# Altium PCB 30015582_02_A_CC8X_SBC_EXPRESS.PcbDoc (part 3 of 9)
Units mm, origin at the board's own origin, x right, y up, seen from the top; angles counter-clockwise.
Board outline 87 x 63 mm, 6 copper layers (Top Layer-L1, GND Plane-L2, Signal-L3, PWR/Signal-L4, GND Plane-L5, Bottom Layer-L6), stack 1.172 mm thick; 169 components, 171 nets, 693 pads, 391 vias.
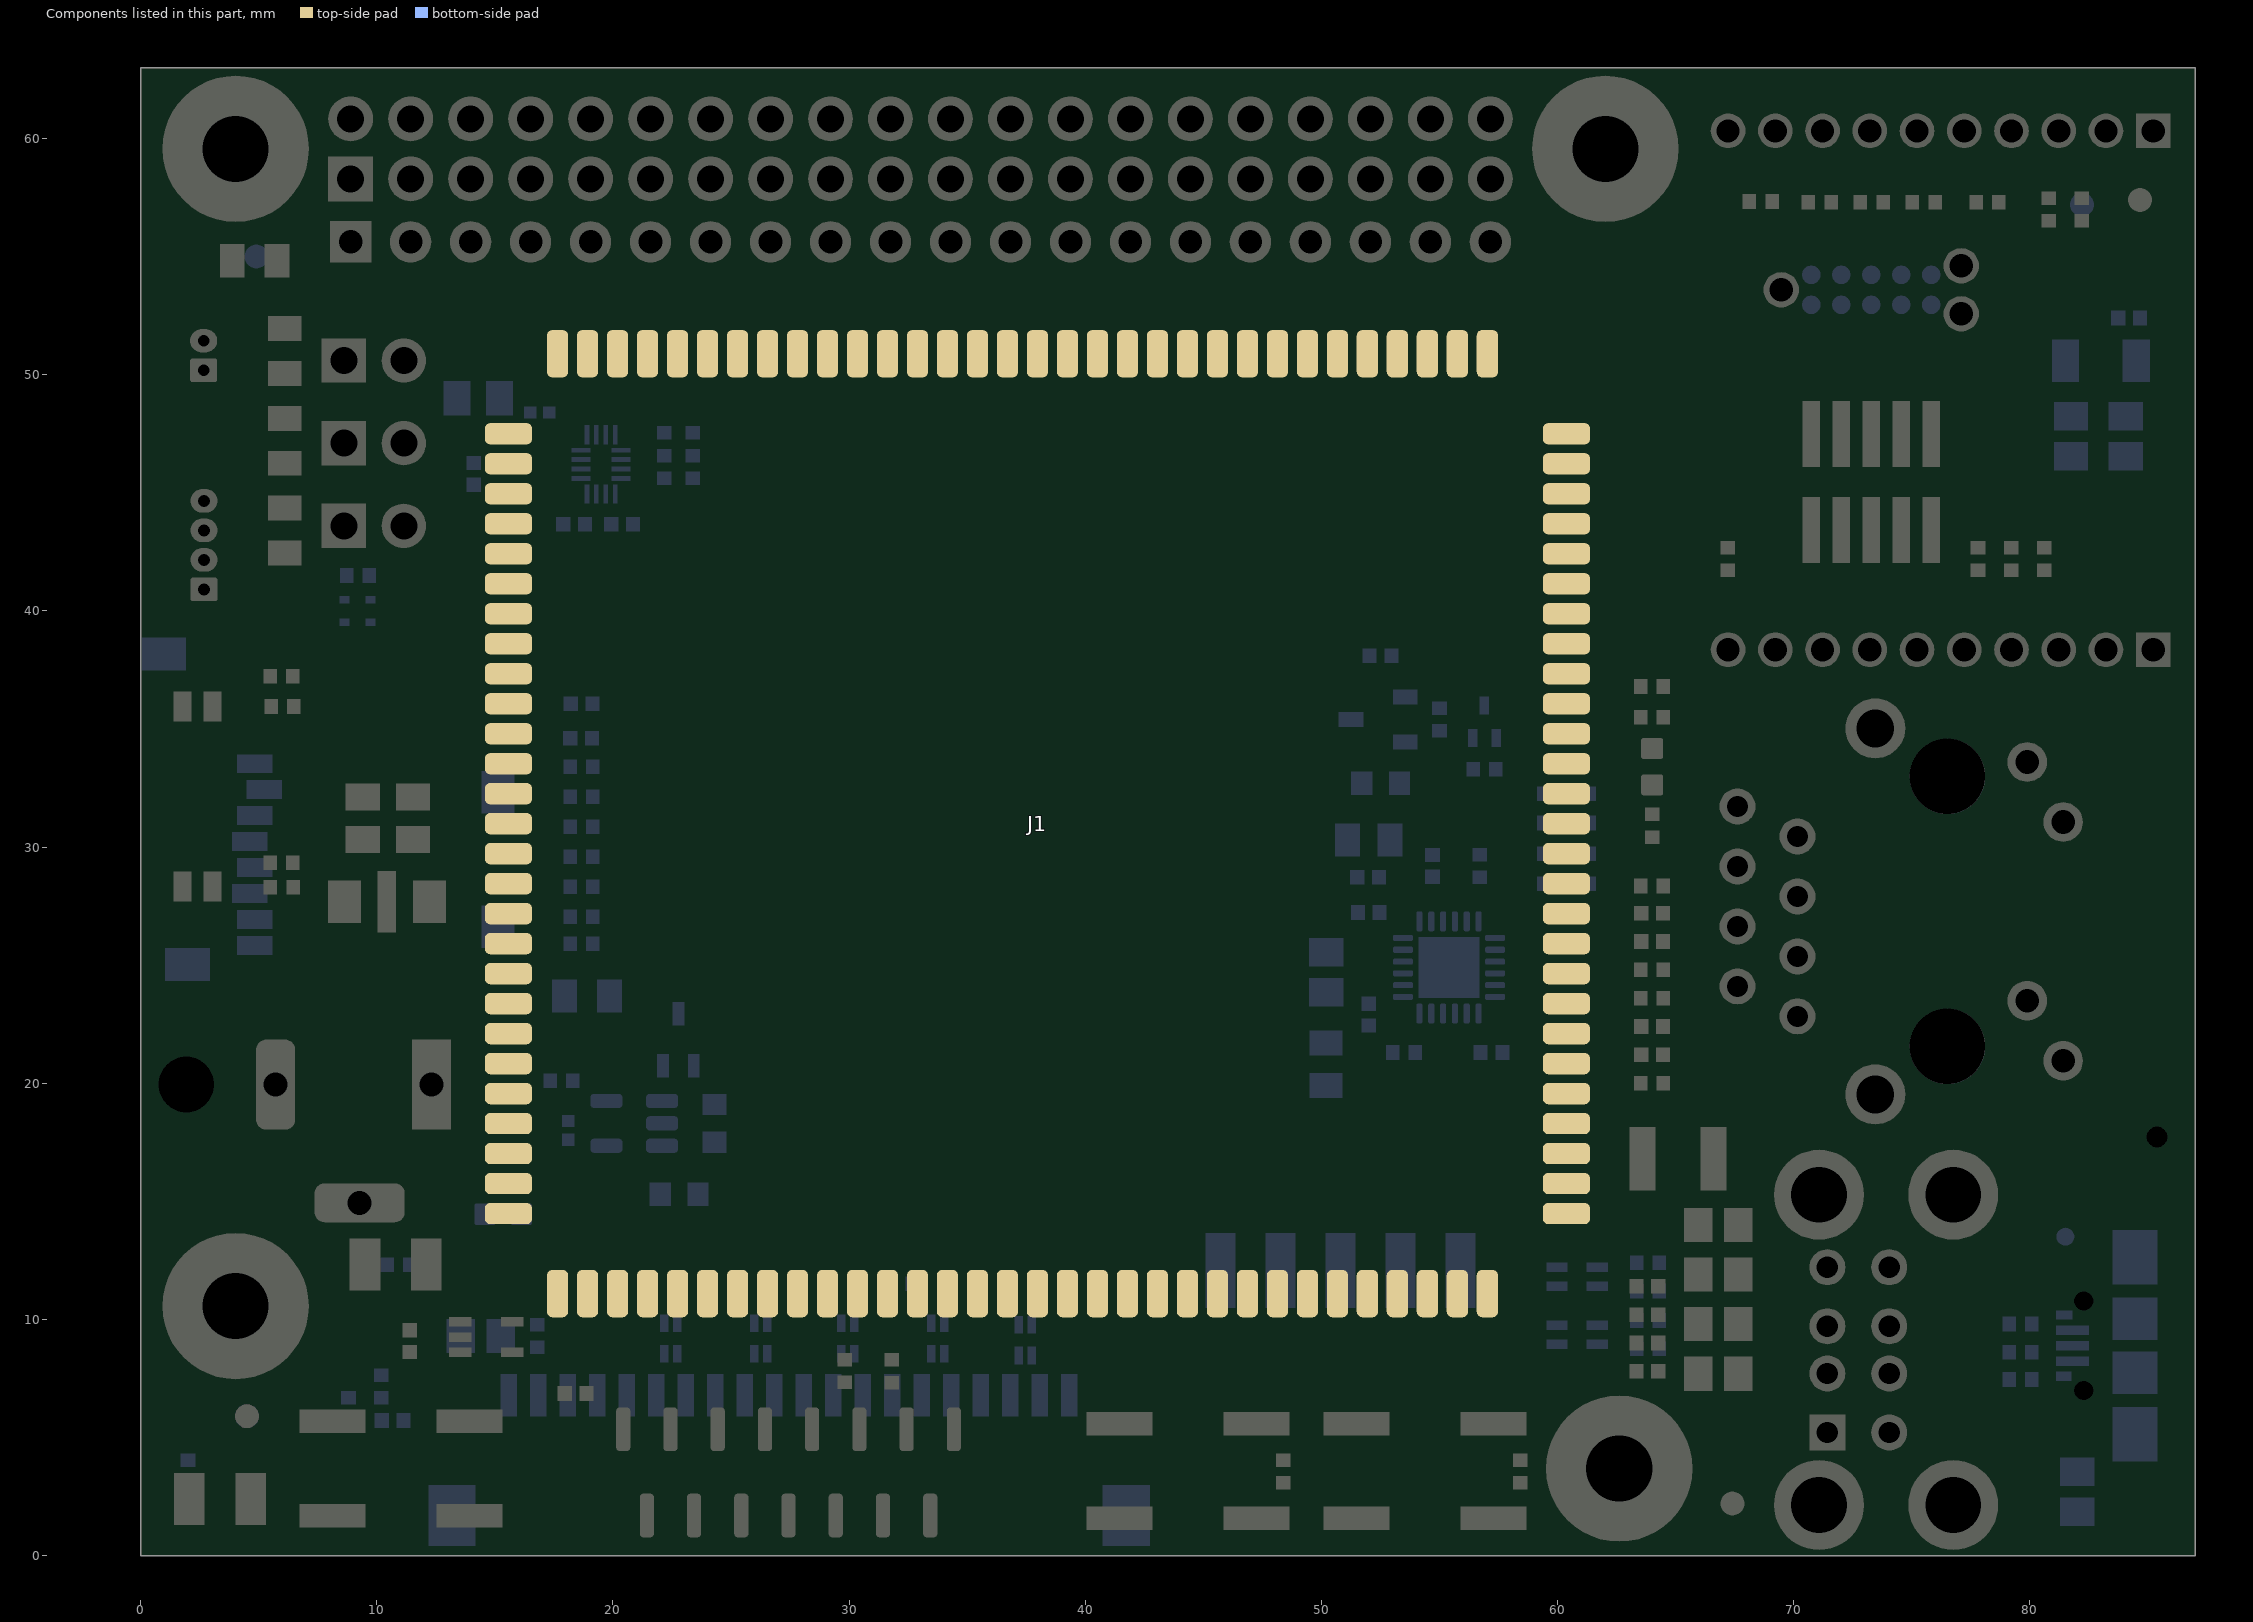
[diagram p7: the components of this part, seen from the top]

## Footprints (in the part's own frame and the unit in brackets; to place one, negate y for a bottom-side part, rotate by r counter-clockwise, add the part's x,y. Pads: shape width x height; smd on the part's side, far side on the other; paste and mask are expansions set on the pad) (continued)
CC8X_CASTELLATED [mm] (continued)
  Top Layer-L1 keep-out region: 4.01,-15.24 3.995,-15.317 3.951,-15.381 3.887,-15.425 3.81,-15.44 3.81,-15.44 3.733,-15.425 3.669,-15.381 3.625,-15.317 3.61,-15.24 3.61,-15.24 3.625,-15.163 3.669,-15.099 3.733,-15.055 3.81,-15.04 3.81,-15.04 3.887,-15.055 3.951,-15.099 3.995,-15.163 4.01,-15.24
  Top Layer-L1 keep-out region: 2.74,-15.24 2.725,-15.317 2.681,-15.381 2.617,-15.425 2.54,-15.44 2.54,-15.44 2.463,-15.425 2.399,-15.381 2.355,-15.317 2.34,-15.24 2.34,-15.24 2.355,-15.163 2.399,-15.099 2.463,-15.055 2.54,-15.04 2.54,-15.04 2.617,-15.055 2.681,-15.099 2.725,-15.163 2.74,-15.24
  Top Layer-L1 keep-out region: 1.47,-15.24 1.455,-15.317 1.411,-15.381 1.347,-15.425 1.27,-15.44 1.27,-15.44 1.193,-15.425 1.129,-15.381 1.085,-15.317 1.07,-15.24 1.07,-15.24 1.085,-15.163 1.129,-15.099 1.193,-15.055 1.27,-15.04 1.27,-15.04 1.347,-15.055 1.411,-15.099 1.455,-15.163 1.47,-15.24
  Top Layer-L1 keep-out region: 0.2,-15.24 0.185,-15.317 0.141,-15.381 0.077,-15.425 0,-15.44 0,-15.44 -0.077,-15.425 -0.141,-15.381 -0.185,-15.317 -0.2,-15.24 -0.2,-15.24 -0.185,-15.163 -0.141,-15.099 -0.077,-15.055 0,-15.04 0,-15.04 0.077,-15.055 0.141,-15.099 0.185,-15.163 0.2,-15.24
  Top Layer-L1 keep-out region: -1.07,-15.24 -1.085,-15.317 -1.129,-15.381 -1.193,-15.425 -1.27,-15.44 -1.27,-15.44 -1.347,-15.425 -1.411,-15.381 -1.455,-15.317 -1.47,-15.24 -1.47,-15.24 -1.455,-15.163 -1.411,-15.099 -1.347,-15.055 -1.27,-15.04 -1.27,-15.04 -1.193,-15.055 -1.129,-15.099 -1.085,-15.163 -1.07,-15.24
  Top Layer-L1 keep-out region: -2.34,-15.24 -2.355,-15.317 -2.399,-15.381 -2.463,-15.425 -2.54,-15.44 -2.54,-15.44 -2.617,-15.425 -2.681,-15.381 -2.725,-15.317 -2.74,-15.24 -2.74,-15.24 -2.725,-15.163 -2.681,-15.099 -2.617,-15.055 -2.54,-15.04 -2.54,-15.04 -2.463,-15.055 -2.399,-15.099 -2.355,-15.163 -2.34,-15.24
  Top Layer-L1 keep-out region: -3.61,-15.24 -3.625,-15.317 -3.669,-15.381 -3.733,-15.425 -3.81,-15.44 -3.81,-15.44 -3.887,-15.425 -3.951,-15.381 -3.995,-15.317 -4.01,-15.24 -4.01,-15.24 -3.995,-15.163 -3.951,-15.099 -3.887,-15.055 -3.81,-15.04 -3.81,-15.04 -3.733,-15.055 -3.669,-15.099 -3.625,-15.163 -3.61,-15.24
  Top Layer-L1 keep-out region: -4.88,-15.24 -4.895,-15.317 -4.939,-15.381 -5.003,-15.425 -5.08,-15.44 -5.08,-15.44 -5.157,-15.425 -5.221,-15.381 -5.265,-15.317 -5.28,-15.24 -5.28,-15.24 -5.265,-15.163 -5.221,-15.099 -5.157,-15.055 -5.08,-15.04 -5.08,-15.04 -5.003,-15.055 -4.939,-15.099 -4.895,-15.163 -4.88,-15.24
  Top Layer-L1 keep-out region: -6.15,-15.24 -6.165,-15.317 -6.209,-15.381 -6.273,-15.425 -6.35,-15.44 -6.35,-15.44 -6.427,-15.425 -6.491,-15.381 -6.535,-15.317 -6.55,-15.24 -6.55,-15.24 -6.535,-15.163 -6.491,-15.099 -6.427,-15.055 -6.35,-15.04 -6.35,-15.04 -6.273,-15.055 -6.209,-15.099 -6.165,-15.163 -6.15,-15.24
  Top Layer-L1 keep-out region: -7.42,-15.24 -7.435,-15.317 -7.479,-15.381 -7.543,-15.425 -7.62,-15.44 -7.62,-15.44 -7.697,-15.425 -7.761,-15.381 -7.805,-15.317 -7.82,-15.24 -7.82,-15.24 -7.805,-15.163 -7.761,-15.099 -7.697,-15.055 -7.62,-15.04 -7.62,-15.04 -7.543,-15.055 -7.479,-15.099 -7.435,-15.163 -7.42,-15.24
  Top Layer-L1 keep-out region: -8.69,-15.24 -8.705,-15.317 -8.749,-15.381 -8.813,-15.425 -8.89,-15.44 -8.89,-15.44 -8.967,-15.425 -9.031,-15.381 -9.075,-15.317 -9.09,-15.24 -9.09,-15.24 -9.075,-15.163 -9.031,-15.099 -8.967,-15.055 -8.89,-15.04 -8.89,-15.04 -8.813,-15.055 -8.749,-15.099 -8.705,-15.163 -8.69,-15.24
  Top Layer-L1 keep-out region: -9.96,-15.24 -9.975,-15.317 -10.019,-15.381 -10.083,-15.425 -10.16,-15.44 -10.16,-15.44 -10.237,-15.425 -10.301,-15.381 -10.345,-15.317 -10.36,-15.24 -10.36,-15.24 -10.345,-15.163 -10.301,-15.099 -10.237,-15.055 -10.16,-15.04 -10.16,-15.04 -10.083,-15.055 -10.019,-15.099 -9.975,-15.163 -9.96,-15.24
  Top Layer-L1 keep-out region: -11.23,-15.24 -11.245,-15.317 -11.289,-15.381 -11.353,-15.425 -11.43,-15.44 -11.43,-15.44 -11.507,-15.425 -11.571,-15.381 -11.615,-15.317 -11.63,-15.24 -11.63,-15.24 -11.615,-15.163 -11.571,-15.099 -11.507,-15.055 -11.43,-15.04 -11.43,-15.04 -11.353,-15.055 -11.289,-15.099 -11.245,-15.163 -11.23,-15.24
  Top Layer-L1 keep-out region: -12.5,-15.24 -12.515,-15.317 -12.559,-15.381 -12.623,-15.425 -12.7,-15.44 -12.7,-15.44 -12.777,-15.425 -12.841,-15.381 -12.885,-15.317 -12.9,-15.24 -12.9,-15.24 -12.885,-15.163 -12.841,-15.099 -12.777,-15.055 -12.7,-15.04 -12.7,-15.04 -12.623,-15.055 -12.559,-15.099 -12.515,-15.163 -12.5,-15.24
  Top Layer-L1 keep-out region: -13.77,-15.24 -13.785,-15.317 -13.829,-15.381 -13.893,-15.425 -13.97,-15.44 -13.97,-15.44 -14.047,-15.425 -14.111,-15.381 -14.155,-15.317 -14.17,-15.24 -14.17,-15.24 -14.155,-15.163 -14.111,-15.099 -14.047,-15.055 -13.97,-15.04 -13.97,-15.04 -13.893,-15.055 -13.829,-15.099 -13.785,-15.163 -13.77,-15.24
  Top Layer-L1 keep-out region: -15.04,-15.24 -15.055,-15.317 -15.099,-15.381 -15.163,-15.425 -15.24,-15.44 -15.24,-15.44 -15.317,-15.425 -15.381,-15.381 -15.425,-15.317 -15.44,-15.24 -15.44,-15.24 -15.425,-15.163 -15.381,-15.099 -15.317,-15.055 -15.24,-15.04 -15.24,-15.04 -15.163,-15.055 -15.099,-15.099 -15.055,-15.163 -15.04,-15.24
  Top Layer-L1 keep-out region: -16.31,-15.24 -16.325,-15.317 -16.369,-15.381 -16.433,-15.425 -16.51,-15.44 -16.51,-15.44 -16.587,-15.425 -16.651,-15.381 -16.695,-15.317 -16.71,-15.24 -16.71,-15.24 -16.695,-15.163 -16.651,-15.099 -16.587,-15.055 -16.51,-15.04 -16.51,-15.04 -16.433,-15.055 -16.369,-15.099 -16.325,-15.163 -16.31,-15.24
  Top Layer-L1 keep-out region: -17.58,-15.24 -17.595,-15.317 -17.639,-15.381 -17.703,-15.425 -17.78,-15.44 -17.78,-15.44 -17.857,-15.425 -17.921,-15.381 -17.965,-15.317 -17.98,-15.24 -17.98,-15.24 -17.965,-15.163 -17.921,-15.099 -17.857,-15.055 -17.78,-15.04 -17.78,-15.04 -17.703,-15.055 -17.639,-15.099 -17.595,-15.163 -17.58,-15.24
  Top Layer-L1 keep-out region: 17.98,-13.97 17.965,-14.047 17.921,-14.111 17.857,-14.155 17.78,-14.17 17.78,-14.17 17.703,-14.155 17.639,-14.111 17.595,-14.047 17.58,-13.97 17.58,-13.97 17.595,-13.893 17.639,-13.829 17.703,-13.785 17.78,-13.77 17.78,-13.77 17.857,-13.785 17.921,-13.829 17.965,-13.893 17.98,-13.97
  Top Layer-L1 keep-out region: 16.71,-13.97 16.695,-14.047 16.651,-14.111 16.587,-14.155 16.51,-14.17 16.51,-14.17 16.433,-14.155 16.369,-14.111 16.325,-14.047 16.31,-13.97 16.31,-13.97 16.325,-13.893 16.369,-13.829 16.433,-13.785 16.51,-13.77 16.51,-13.77 16.587,-13.785 16.651,-13.829 16.695,-13.893 16.71,-13.97
  Top Layer-L1 keep-out region: 15.44,-13.97 15.425,-14.047 15.381,-14.111 15.317,-14.155 15.24,-14.17 15.24,-14.17 15.163,-14.155 15.099,-14.111 15.055,-14.047 15.04,-13.97 15.04,-13.97 15.055,-13.893 15.099,-13.829 15.163,-13.785 15.24,-13.77 15.24,-13.77 15.317,-13.785 15.381,-13.829 15.425,-13.893 15.44,-13.97
  Top Layer-L1 keep-out region: 14.17,-13.97 14.155,-14.047 14.111,-14.111 14.047,-14.155 13.97,-14.17 13.97,-14.17 13.893,-14.155 13.829,-14.111 13.785,-14.047 13.77,-13.97 13.77,-13.97 13.785,-13.893 13.829,-13.829 13.893,-13.785 13.97,-13.77 13.97,-13.77 14.047,-13.785 14.111,-13.829 14.155,-13.893 14.17,-13.97
  Top Layer-L1 keep-out region: 12.9,-13.97 12.885,-14.047 12.841,-14.111 12.777,-14.155 12.7,-14.17 12.7,-14.17 12.623,-14.155 12.559,-14.111 12.515,-14.047 12.5,-13.97 12.5,-13.97 12.515,-13.893 12.559,-13.829 12.623,-13.785 12.7,-13.77 12.7,-13.77 12.777,-13.785 12.841,-13.829 12.885,-13.893 12.9,-13.97
  Top Layer-L1 keep-out region: 11.63,-13.97 11.615,-14.047 11.571,-14.111 11.507,-14.155 11.43,-14.17 11.43,-14.17 11.353,-14.155 11.289,-14.111 11.245,-14.047 11.23,-13.97 11.23,-13.97 11.245,-13.893 11.289,-13.829 11.353,-13.785 11.43,-13.77 11.43,-13.77 11.507,-13.785 11.571,-13.829 11.615,-13.893 11.63,-13.97
  Top Layer-L1 keep-out region: 10.36,-13.97 10.345,-14.047 10.301,-14.111 10.237,-14.155 10.16,-14.17 10.16,-14.17 10.083,-14.155 10.019,-14.111 9.975,-14.047 9.96,-13.97 9.96,-13.97 9.975,-13.893 10.019,-13.829 10.083,-13.785 10.16,-13.77 10.16,-13.77 10.237,-13.785 10.301,-13.829 10.345,-13.893 10.36,-13.97
  Top Layer-L1 keep-out region: 9.09,-13.97 9.075,-14.047 9.031,-14.111 8.967,-14.155 8.89,-14.17 8.89,-14.17 8.813,-14.155 8.749,-14.111 8.705,-14.047 8.69,-13.97 8.69,-13.97 8.705,-13.893 8.749,-13.829 8.813,-13.785 8.89,-13.77 8.89,-13.77 8.967,-13.785 9.031,-13.829 9.075,-13.893 9.09,-13.97
  Top Layer-L1 keep-out region: 7.82,-13.97 7.805,-14.047 7.761,-14.111 7.697,-14.155 7.62,-14.17 7.62,-14.17 7.543,-14.155 7.479,-14.111 7.435,-14.047 7.42,-13.97 7.42,-13.97 7.435,-13.893 7.479,-13.829 7.543,-13.785 7.62,-13.77 7.62,-13.77 7.697,-13.785 7.761,-13.829 7.805,-13.893 7.82,-13.97
  Top Layer-L1 keep-out region: 6.55,-13.97 6.535,-14.047 6.491,-14.111 6.427,-14.155 6.35,-14.17 6.35,-14.17 6.273,-14.155 6.209,-14.111 6.165,-14.047 6.15,-13.97 6.15,-13.97 6.165,-13.893 6.209,-13.829 6.273,-13.785 6.35,-13.77 6.35,-13.77 6.427,-13.785 6.491,-13.829 6.535,-13.893 6.55,-13.97
  Top Layer-L1 keep-out region: 5.28,-13.97 5.265,-14.047 5.221,-14.111 5.157,-14.155 5.08,-14.17 5.08,-14.17 5.003,-14.155 4.939,-14.111 4.895,-14.047 4.88,-13.97 4.88,-13.97 4.895,-13.893 4.939,-13.829 5.003,-13.785 5.08,-13.77 5.08,-13.77 5.157,-13.785 5.221,-13.829 5.265,-13.893 5.28,-13.97
  Top Layer-L1 keep-out region: 4.01,-13.97 3.995,-14.047 3.951,-14.111 3.887,-14.155 3.81,-14.17 3.81,-14.17 3.733,-14.155 3.669,-14.111 3.625,-14.047 3.61,-13.97 3.61,-13.97 3.625,-13.893 3.669,-13.829 3.733,-13.785 3.81,-13.77 3.81,-13.77 3.887,-13.785 3.951,-13.829 3.995,-13.893 4.01,-13.97
  Top Layer-L1 keep-out region: 2.74,-13.97 2.725,-14.047 2.681,-14.111 2.617,-14.155 2.54,-14.17 2.54,-14.17 2.463,-14.155 2.399,-14.111 2.355,-14.047 2.34,-13.97 2.34,-13.97 2.355,-13.893 2.399,-13.829 2.463,-13.785 2.54,-13.77 2.54,-13.77 2.617,-13.785 2.681,-13.829 2.725,-13.893 2.74,-13.97
  Top Layer-L1 keep-out region: 1.47,-13.97 1.455,-14.047 1.411,-14.111 1.347,-14.155 1.27,-14.17 1.27,-14.17 1.193,-14.155 1.129,-14.111 1.085,-14.047 1.07,-13.97 1.07,-13.97 1.085,-13.893 1.129,-13.829 1.193,-13.785 1.27,-13.77 1.27,-13.77 1.347,-13.785 1.411,-13.829 1.455,-13.893 1.47,-13.97
  Top Layer-L1 keep-out region: 0.2,-13.97 0.185,-14.047 0.141,-14.111 0.077,-14.155 0,-14.17 0,-14.17 -0.077,-14.155 -0.141,-14.111 -0.185,-14.047 -0.2,-13.97 -0.2,-13.97 -0.185,-13.893 -0.141,-13.829 -0.077,-13.785 0,-13.77 0,-13.77 0.077,-13.785 0.141,-13.829 0.185,-13.893 0.2,-13.97
  Top Layer-L1 keep-out region: -1.07,-13.97 -1.085,-14.047 -1.129,-14.111 -1.193,-14.155 -1.27,-14.17 -1.27,-14.17 -1.347,-14.155 -1.411,-14.111 -1.455,-14.047 -1.47,-13.97 -1.47,-13.97 -1.455,-13.893 -1.411,-13.829 -1.347,-13.785 -1.27,-13.77 -1.27,-13.77 -1.193,-13.785 -1.129,-13.829 -1.085,-13.893 -1.07,-13.97
  Top Layer-L1 keep-out region: -2.34,-13.97 -2.355,-14.047 -2.399,-14.111 -2.463,-14.155 -2.54,-14.17 -2.54,-14.17 -2.617,-14.155 -2.681,-14.111 -2.725,-14.047 -2.74,-13.97 -2.74,-13.97 -2.725,-13.893 -2.681,-13.829 -2.617,-13.785 -2.54,-13.77 -2.54,-13.77 -2.463,-13.785 -2.399,-13.829 -2.355,-13.893 -2.34,-13.97
  Top Layer-L1 keep-out region: -3.61,-13.97 -3.625,-14.047 -3.669,-14.111 -3.733,-14.155 -3.81,-14.17 -3.81,-14.17 -3.887,-14.155 -3.951,-14.111 -3.995,-14.047 -4.01,-13.97 -4.01,-13.97 -3.995,-13.893 -3.951,-13.829 -3.887,-13.785 -3.81,-13.77 -3.81,-13.77 -3.733,-13.785 -3.669,-13.829 -3.625,-13.893 -3.61,-13.97
  Top Layer-L1 keep-out region: -4.88,-13.97 -4.895,-14.047 -4.939,-14.111 -5.003,-14.155 -5.08,-14.17 -5.08,-14.17 -5.157,-14.155 -5.221,-14.111 -5.265,-14.047 -5.28,-13.97 -5.28,-13.97 -5.265,-13.893 -5.221,-13.829 -5.157,-13.785 -5.08,-13.77 -5.08,-13.77 -5.003,-13.785 -4.939,-13.829 -4.895,-13.893 -4.88,-13.97
  Top Layer-L1 keep-out region: -6.15,-13.97 -6.165,-14.047 -6.209,-14.111 -6.273,-14.155 -6.35,-14.17 -6.35,-14.17 -6.427,-14.155 -6.491,-14.111 -6.535,-14.047 -6.55,-13.97 -6.55,-13.97 -6.535,-13.893 -6.491,-13.829 -6.427,-13.785 -6.35,-13.77 -6.35,-13.77 -6.273,-13.785 -6.209,-13.829 -6.165,-13.893 -6.15,-13.97
  Top Layer-L1 keep-out region: -7.42,-13.97 -7.435,-14.047 -7.479,-14.111 -7.543,-14.155 -7.62,-14.17 -7.62,-14.17 -7.697,-14.155 -7.761,-14.111 -7.805,-14.047 -7.82,-13.97 -7.82,-13.97 -7.805,-13.893 -7.761,-13.829 -7.697,-13.785 -7.62,-13.77 -7.62,-13.77 -7.543,-13.785 -7.479,-13.829 -7.435,-13.893 -7.42,-13.97
  Top Layer-L1 keep-out region: -8.69,-13.97 -8.705,-14.047 -8.749,-14.111 -8.813,-14.155 -8.89,-14.17 -8.89,-14.17 -8.967,-14.155 -9.031,-14.111 -9.075,-14.047 -9.09,-13.97 -9.09,-13.97 -9.075,-13.893 -9.031,-13.829 -8.967,-13.785 -8.89,-13.77 -8.89,-13.77 -8.813,-13.785 -8.749,-13.829 -8.705,-13.893 -8.69,-13.97
  Top Layer-L1 keep-out region: -9.96,-13.97 -9.975,-14.047 -10.019,-14.111 -10.083,-14.155 -10.16,-14.17 -10.16,-14.17 -10.237,-14.155 -10.301,-14.111 -10.345,-14.047 -10.36,-13.97 -10.36,-13.97 -10.345,-13.893 -10.301,-13.829 -10.237,-13.785 -10.16,-13.77 -10.16,-13.77 -10.083,-13.785 -10.019,-13.829 -9.975,-13.893 -9.96,-13.97
  Top Layer-L1 keep-out region: -11.23,-13.97 -11.245,-14.047 -11.289,-14.111 -11.353,-14.155 -11.43,-14.17 -11.43,-14.17 -11.507,-14.155 -11.571,-14.111 -11.615,-14.047 -11.63,-13.97 -11.63,-13.97 -11.615,-13.893 -11.571,-13.829 -11.507,-13.785 -11.43,-13.77 -11.43,-13.77 -11.353,-13.785 -11.289,-13.829 -11.245,-13.893 -11.23,-13.97
  Top Layer-L1 keep-out region: -12.5,-13.97 -12.515,-14.047 -12.559,-14.111 -12.623,-14.155 -12.7,-14.17 -12.7,-14.17 -12.777,-14.155 -12.841,-14.111 -12.885,-14.047 -12.9,-13.97 -12.9,-13.97 -12.885,-13.893 -12.841,-13.829 -12.777,-13.785 -12.7,-13.77 -12.7,-13.77 -12.623,-13.785 -12.559,-13.829 -12.515,-13.893 -12.5,-13.97
  Top Layer-L1 keep-out region: -13.77,-13.97 -13.785,-14.047 -13.829,-14.111 -13.893,-14.155 -13.97,-14.17 -13.97,-14.17 -14.047,-14.155 -14.111,-14.111 -14.155,-14.047 -14.17,-13.97 -14.17,-13.97 -14.155,-13.893 -14.111,-13.829 -14.047,-13.785 -13.97,-13.77 -13.97,-13.77 -13.893,-13.785 -13.829,-13.829 -13.785,-13.893 -13.77,-13.97
  Top Layer-L1 keep-out region: -15.04,-13.97 -15.055,-14.047 -15.099,-14.111 -15.163,-14.155 -15.24,-14.17 -15.24,-14.17 -15.317,-14.155 -15.381,-14.111 -15.425,-14.047 -15.44,-13.97 -15.44,-13.97 -15.425,-13.893 -15.381,-13.829 -15.317,-13.785 -15.24,-13.77 -15.24,-13.77 -15.163,-13.785 -15.099,-13.829 -15.055,-13.893 -15.04,-13.97
  Top Layer-L1 keep-out region: -16.31,-13.97 -16.325,-14.047 -16.369,-14.111 -16.433,-14.155 -16.51,-14.17 -16.51,-14.17 -16.587,-14.155 -16.651,-14.111 -16.695,-14.047 -16.71,-13.97 -16.71,-13.97 -16.695,-13.893 -16.651,-13.829 -16.587,-13.785 -16.51,-13.77 -16.51,-13.77 -16.433,-13.785 -16.369,-13.829 -16.325,-13.893 -16.31,-13.97
  Top Layer-L1 keep-out region: -17.58,-13.97 -17.595,-14.047 -17.639,-14.111 -17.703,-14.155 -17.78,-14.17 -17.78,-14.17 -17.857,-14.155 -17.921,-14.111 -17.965,-14.047 -17.98,-13.97 -17.98,-13.97 -17.965,-13.893 -17.921,-13.829 -17.857,-13.785 -17.78,-13.77 -17.78,-13.77 -17.703,-13.785 -17.639,-13.829 -17.595,-13.893 -17.58,-13.97
  Top Layer-L1 keep-out region: 17.98,-12.7 17.965,-12.777 17.921,-12.841 17.857,-12.885 17.78,-12.9 17.78,-12.9 17.703,-12.885 17.639,-12.841 17.595,-12.777 17.58,-12.7 17.58,-12.7 17.595,-12.623 17.639,-12.559 17.703,-12.515 17.78,-12.5 17.78,-12.5 17.857,-12.515 17.921,-12.559 17.965,-12.623 17.98,-12.7
  Top Layer-L1 keep-out region: 16.71,-12.7 16.695,-12.777 16.651,-12.841 16.587,-12.885 16.51,-12.9 16.51,-12.9 16.433,-12.885 16.369,-12.841 16.325,-12.777 16.31,-12.7 16.31,-12.7 16.325,-12.623 16.369,-12.559 16.433,-12.515 16.51,-12.5 16.51,-12.5 16.587,-12.515 16.651,-12.559 16.695,-12.623 16.71,-12.7
  Top Layer-L1 keep-out region: 15.44,-12.7 15.425,-12.777 15.381,-12.841 15.317,-12.885 15.24,-12.9 15.24,-12.9 15.163,-12.885 15.099,-12.841 15.055,-12.777 15.04,-12.7 15.04,-12.7 15.055,-12.623 15.099,-12.559 15.163,-12.515 15.24,-12.5 15.24,-12.5 15.317,-12.515 15.381,-12.559 15.425,-12.623 15.44,-12.7
  Top Layer-L1 keep-out region: 14.17,-12.7 14.155,-12.777 14.111,-12.841 14.047,-12.885 13.97,-12.9 13.97,-12.9 13.893,-12.885 13.829,-12.841 13.785,-12.777 13.77,-12.7 13.77,-12.7 13.785,-12.623 13.829,-12.559 13.893,-12.515 13.97,-12.5 13.97,-12.5 14.047,-12.515 14.111,-12.559 14.155,-12.623 14.17,-12.7
  Top Layer-L1 keep-out region: 12.9,-12.7 12.885,-12.777 12.841,-12.841 12.777,-12.885 12.7,-12.9 12.7,-12.9 12.623,-12.885 12.559,-12.841 12.515,-12.777 12.5,-12.7 12.5,-12.7 12.515,-12.623 12.559,-12.559 12.623,-12.515 12.7,-12.5 12.7,-12.5 12.777,-12.515 12.841,-12.559 12.885,-12.623 12.9,-12.7
  Top Layer-L1 keep-out region: 11.63,-12.7 11.615,-12.777 11.571,-12.841 11.507,-12.885 11.43,-12.9 11.43,-12.9 11.353,-12.885 11.289,-12.841 11.245,-12.777 11.23,-12.7 11.23,-12.7 11.245,-12.623 11.289,-12.559 11.353,-12.515 11.43,-12.5 11.43,-12.5 11.507,-12.515 11.571,-12.559 11.615,-12.623 11.63,-12.7
  Top Layer-L1 keep-out region: 10.36,-12.7 10.345,-12.777 10.301,-12.841 10.237,-12.885 10.16,-12.9 10.16,-12.9 10.083,-12.885 10.019,-12.841 9.975,-12.777 9.96,-12.7 9.96,-12.7 9.975,-12.623 10.019,-12.559 10.083,-12.515 10.16,-12.5 10.16,-12.5 10.237,-12.515 10.301,-12.559 10.345,-12.623 10.36,-12.7
  Top Layer-L1 keep-out region: 9.09,-12.7 9.075,-12.777 9.031,-12.841 8.967,-12.885 8.89,-12.9 8.89,-12.9 8.813,-12.885 8.749,-12.841 8.705,-12.777 8.69,-12.7 8.69,-12.7 8.705,-12.623 8.749,-12.559 8.813,-12.515 8.89,-12.5 8.89,-12.5 8.967,-12.515 9.031,-12.559 9.075,-12.623 9.09,-12.7
  Top Layer-L1 keep-out region: 7.82,-12.7 7.805,-12.777 7.761,-12.841 7.697,-12.885 7.62,-12.9 7.62,-12.9 7.543,-12.885 7.479,-12.841 7.435,-12.777 7.42,-12.7 7.42,-12.7 7.435,-12.623 7.479,-12.559 7.543,-12.515 7.62,-12.5 7.62,-12.5 7.697,-12.515 7.761,-12.559 7.805,-12.623 7.82,-12.7
  Top Layer-L1 keep-out region: 6.55,-12.7 6.535,-12.777 6.491,-12.841 6.427,-12.885 6.35,-12.9 6.35,-12.9 6.273,-12.885 6.209,-12.841 6.165,-12.777 6.15,-12.7 6.15,-12.7 6.165,-12.623 6.209,-12.559 6.273,-12.515 6.35,-12.5 6.35,-12.5 6.427,-12.515 6.491,-12.559 6.535,-12.623 6.55,-12.7
  Top Layer-L1 keep-out region: 5.28,-12.7 5.265,-12.777 5.221,-12.841 5.157,-12.885 5.08,-12.9 5.08,-12.9 5.003,-12.885 4.939,-12.841 4.895,-12.777 4.88,-12.7 4.88,-12.7 4.895,-12.623 4.939,-12.559 5.003,-12.515 5.08,-12.5 5.08,-12.5 5.157,-12.515 5.221,-12.559 5.265,-12.623 5.28,-12.7
  Top Layer-L1 keep-out region: 4.01,-12.7 3.995,-12.777 3.951,-12.841 3.887,-12.885 3.81,-12.9 3.81,-12.9 3.733,-12.885 3.669,-12.841 3.625,-12.777 3.61,-12.7 3.61,-12.7 3.625,-12.623 3.669,-12.559 3.733,-12.515 3.81,-12.5 3.81,-12.5 3.887,-12.515 3.951,-12.559 3.995,-12.623 4.01,-12.7
  Top Layer-L1 keep-out region: 2.74,-12.7 2.725,-12.777 2.681,-12.841 2.617,-12.885 2.54,-12.9 2.54,-12.9 2.463,-12.885 2.399,-12.841 2.355,-12.777 2.34,-12.7 2.34,-12.7 2.355,-12.623 2.399,-12.559 2.463,-12.515 2.54,-12.5 2.54,-12.5 2.617,-12.515 2.681,-12.559 2.725,-12.623 2.74,-12.7
  Top Layer-L1 keep-out region: 1.47,-12.7 1.455,-12.777 1.411,-12.841 1.347,-12.885 1.27,-12.9 1.27,-12.9 1.193,-12.885 1.129,-12.841 1.085,-12.777 1.07,-12.7 1.07,-12.7 1.085,-12.623 1.129,-12.559 1.193,-12.515 1.27,-12.5 1.27,-12.5 1.347,-12.515 1.411,-12.559 1.455,-12.623 1.47,-12.7
  Top Layer-L1 keep-out region: 0.2,-12.7 0.185,-12.777 0.141,-12.841 0.077,-12.885 0,-12.9 0,-12.9 -0.077,-12.885 -0.141,-12.841 -0.185,-12.777 -0.2,-12.7 -0.2,-12.7 -0.185,-12.623 -0.141,-12.559 -0.077,-12.515 0,-12.5 0,-12.5 0.077,-12.515 0.141,-12.559 0.185,-12.623 0.2,-12.7
  Top Layer-L1 keep-out region: -1.07,-12.7 -1.085,-12.777 -1.129,-12.841 -1.193,-12.885 -1.27,-12.9 -1.27,-12.9 -1.347,-12.885 -1.411,-12.841 -1.455,-12.777 -1.47,-12.7 -1.47,-12.7 -1.455,-12.623 -1.411,-12.559 -1.347,-12.515 -1.27,-12.5 -1.27,-12.5 -1.193,-12.515 -1.129,-12.559 -1.085,-12.623 -1.07,-12.7
  Top Layer-L1 keep-out region: -2.34,-12.7 -2.355,-12.777 -2.399,-12.841 -2.463,-12.885 -2.54,-12.9 -2.54,-12.9 -2.617,-12.885 -2.681,-12.841 -2.725,-12.777 -2.74,-12.7 -2.74,-12.7 -2.725,-12.623 -2.681,-12.559 -2.617,-12.515 -2.54,-12.5 -2.54,-12.5 -2.463,-12.515 -2.399,-12.559 -2.355,-12.623 -2.34,-12.7
  Top Layer-L1 keep-out region: -3.61,-12.7 -3.625,-12.777 -3.669,-12.841 -3.733,-12.885 -3.81,-12.9 -3.81,-12.9 -3.887,-12.885 -3.951,-12.841 -3.995,-12.777 -4.01,-12.7 -4.01,-12.7 -3.995,-12.623 -3.951,-12.559 -3.887,-12.515 -3.81,-12.5 -3.81,-12.5 -3.733,-12.515 -3.669,-12.559 -3.625,-12.623 -3.61,-12.7
  Top Layer-L1 keep-out region: -4.88,-12.7 -4.895,-12.777 -4.939,-12.841 -5.003,-12.885 -5.08,-12.9 -5.08,-12.9 -5.157,-12.885 -5.221,-12.841 -5.265,-12.777 -5.28,-12.7 -5.28,-12.7 -5.265,-12.623 -5.221,-12.559 -5.157,-12.515 -5.08,-12.5 -5.08,-12.5 -5.003,-12.515 -4.939,-12.559 -4.895,-12.623 -4.88,-12.7
  Top Layer-L1 keep-out region: -6.15,-12.7 -6.165,-12.777 -6.209,-12.841 -6.273,-12.885 -6.35,-12.9 -6.35,-12.9 -6.427,-12.885 -6.491,-12.841 -6.535,-12.777 -6.55,-12.7 -6.55,-12.7 -6.535,-12.623 -6.491,-12.559 -6.427,-12.515 -6.35,-12.5 -6.35,-12.5 -6.273,-12.515 -6.209,-12.559 -6.165,-12.623 -6.15,-12.7
  Top Layer-L1 keep-out region: -7.42,-12.7 -7.435,-12.777 -7.479,-12.841 -7.543,-12.885 -7.62,-12.9 -7.62,-12.9 -7.697,-12.885 -7.761,-12.841 -7.805,-12.777 -7.82,-12.7 -7.82,-12.7 -7.805,-12.623 -7.761,-12.559 -7.697,-12.515 -7.62,-12.5 -7.62,-12.5 -7.543,-12.515 -7.479,-12.559 -7.435,-12.623 -7.42,-12.7
  Top Layer-L1 keep-out region: -8.69,-12.7 -8.705,-12.777 -8.749,-12.841 -8.813,-12.885 -8.89,-12.9 -8.89,-12.9 -8.967,-12.885 -9.031,-12.841 -9.075,-12.777 -9.09,-12.7 -9.09,-12.7 -9.075,-12.623 -9.031,-12.559 -8.967,-12.515 -8.89,-12.5 -8.89,-12.5 -8.813,-12.515 -8.749,-12.559 -8.705,-12.623 -8.69,-12.7
  Top Layer-L1 keep-out region: -9.96,-12.7 -9.975,-12.777 -10.019,-12.841 -10.083,-12.885 -10.16,-12.9 -10.16,-12.9 -10.237,-12.885 -10.301,-12.841 -10.345,-12.777 -10.36,-12.7 -10.36,-12.7 -10.345,-12.623 -10.301,-12.559 -10.237,-12.515 -10.16,-12.5 -10.16,-12.5 -10.083,-12.515 -10.019,-12.559 -9.975,-12.623 -9.96,-12.7
  Top Layer-L1 keep-out region: -11.23,-12.7 -11.245,-12.777 -11.289,-12.841 -11.353,-12.885 -11.43,-12.9 -11.43,-12.9 -11.507,-12.885 -11.571,-12.841 -11.615,-12.777 -11.63,-12.7 -11.63,-12.7 -11.615,-12.623 -11.571,-12.559 -11.507,-12.515 -11.43,-12.5 -11.43,-12.5 -11.353,-12.515 -11.289,-12.559 -11.245,-12.623 -11.23,-12.7
  Top Layer-L1 keep-out region: -12.5,-12.7 -12.515,-12.777 -12.559,-12.841 -12.623,-12.885 -12.7,-12.9 -12.7,-12.9 -12.777,-12.885 -12.841,-12.841 -12.885,-12.777 -12.9,-12.7 -12.9,-12.7 -12.885,-12.623 -12.841,-12.559 -12.777,-12.515 -12.7,-12.5 -12.7,-12.5 -12.623,-12.515 -12.559,-12.559 -12.515,-12.623 -12.5,-12.7
  Top Layer-L1 keep-out region: -13.77,-12.7 -13.785,-12.777 -13.829,-12.841 -13.893,-12.885 -13.97,-12.9 -13.97,-12.9 -14.047,-12.885 -14.111,-12.841 -14.155,-12.777 -14.17,-12.7 -14.17,-12.7 -14.155,-12.623 -14.111,-12.559 -14.047,-12.515 -13.97,-12.5 -13.97,-12.5 -13.893,-12.515 -13.829,-12.559 -13.785,-12.623 -13.77,-12.7
  Top Layer-L1 keep-out region: -15.04,-12.7 -15.055,-12.777 -15.099,-12.841 -15.163,-12.885 -15.24,-12.9 -15.24,-12.9 -15.317,-12.885 -15.381,-12.841 -15.425,-12.777 -15.44,-12.7 -15.44,-12.7 -15.425,-12.623 -15.381,-12.559 -15.317,-12.515 -15.24,-12.5 -15.24,-12.5 -15.163,-12.515 -15.099,-12.559 -15.055,-12.623 -15.04,-12.7
  Top Layer-L1 keep-out region: -16.31,-12.7 -16.325,-12.777 -16.369,-12.841 -16.433,-12.885 -16.51,-12.9 -16.51,-12.9 -16.587,-12.885 -16.651,-12.841 -16.695,-12.777 -16.71,-12.7 -16.71,-12.7 -16.695,-12.623 -16.651,-12.559 -16.587,-12.515 -16.51,-12.5 -16.51,-12.5 -16.433,-12.515 -16.369,-12.559 -16.325,-12.623 -16.31,-12.7
  Top Layer-L1 keep-out region: -17.58,-12.7 -17.595,-12.777 -17.639,-12.841 -17.703,-12.885 -17.78,-12.9 -17.78,-12.9 -17.857,-12.885 -17.921,-12.841 -17.965,-12.777 -17.98,-12.7 -17.98,-12.7 -17.965,-12.623 -17.921,-12.559 -17.857,-12.515 -17.78,-12.5 -17.78,-12.5 -17.703,-12.515 -17.639,-12.559 -17.595,-12.623 -17.58,-12.7
  Top Layer-L1 keep-out region: 17.98,-11.43 17.965,-11.507 17.921,-11.571 17.857,-11.615 17.78,-11.63 17.78,-11.63 17.703,-11.615 17.639,-11.571 17.595,-11.507 17.58,-11.43 17.58,-11.43 17.595,-11.353 17.639,-11.289 17.703,-11.245 17.78,-11.23 17.78,-11.23 17.857,-11.245 17.921,-11.289 17.965,-11.353 17.98,-11.43
  Top Layer-L1 keep-out region: 16.71,-11.43 16.695,-11.507 16.651,-11.571 16.587,-11.615 16.51,-11.63 16.51,-11.63 16.433,-11.615 16.369,-11.571 16.325,-11.507 16.31,-11.43 16.31,-11.43 16.325,-11.353 16.369,-11.289 16.433,-11.245 16.51,-11.23 16.51,-11.23 16.587,-11.245 16.651,-11.289 16.695,-11.353 16.71,-11.43
  Top Layer-L1 keep-out region: 15.44,-11.43 15.425,-11.507 15.381,-11.571 15.317,-11.615 15.24,-11.63 15.24,-11.63 15.163,-11.615 15.099,-11.571 15.055,-11.507 15.04,-11.43 15.04,-11.43 15.055,-11.353 15.099,-11.289 15.163,-11.245 15.24,-11.23 15.24,-11.23 15.317,-11.245 15.381,-11.289 15.425,-11.353 15.44,-11.43
  Top Layer-L1 keep-out region: 14.17,-11.43 14.155,-11.507 14.111,-11.571 14.047,-11.615 13.97,-11.63 13.97,-11.63 13.893,-11.615 13.829,-11.571 13.785,-11.507 13.77,-11.43 13.77,-11.43 13.785,-11.353 13.829,-11.289 13.893,-11.245 13.97,-11.23 13.97,-11.23 14.047,-11.245 14.111,-11.289 14.155,-11.353 14.17,-11.43
  Top Layer-L1 keep-out region: 12.9,-11.43 12.885,-11.507 12.841,-11.571 12.777,-11.615 12.7,-11.63 12.7,-11.63 12.623,-11.615 12.559,-11.571 12.515,-11.507 12.5,-11.43 12.5,-11.43 12.515,-11.353 12.559,-11.289 12.623,-11.245 12.7,-11.23 12.7,-11.23 12.777,-11.245 12.841,-11.289 12.885,-11.353 12.9,-11.43
  Top Layer-L1 keep-out region: 11.63,-11.43 11.615,-11.507 11.571,-11.571 11.507,-11.615 11.43,-11.63 11.43,-11.63 11.353,-11.615 11.289,-11.571 11.245,-11.507 11.23,-11.43 11.23,-11.43 11.245,-11.353 11.289,-11.289 11.353,-11.245 11.43,-11.23 11.43,-11.23 11.507,-11.245 11.571,-11.289 11.615,-11.353 11.63,-11.43
  Top Layer-L1 keep-out region: 10.36,-11.43 10.345,-11.507 10.301,-11.571 10.237,-11.615 10.16,-11.63 10.16,-11.63 10.083,-11.615 10.019,-11.571 9.975,-11.507 9.96,-11.43 9.96,-11.43 9.975,-11.353 10.019,-11.289 10.083,-11.245 10.16,-11.23 10.16,-11.23 10.237,-11.245 10.301,-11.289 10.345,-11.353 10.36,-11.43
  Top Layer-L1 keep-out region: 9.09,-11.43 9.075,-11.507 9.031,-11.571 8.967,-11.615 8.89,-11.63 8.89,-11.63 8.813,-11.615 8.749,-11.571 8.705,-11.507 8.69,-11.43 8.69,-11.43 8.705,-11.353 8.749,-11.289 8.813,-11.245 8.89,-11.23 8.89,-11.23 8.967,-11.245 9.031,-11.289 9.075,-11.353 9.09,-11.43
  Top Layer-L1 keep-out region: 7.82,-11.43 7.805,-11.507 7.761,-11.571 7.697,-11.615 7.62,-11.63 7.62,-11.63 7.543,-11.615 7.479,-11.571 7.435,-11.507 7.42,-11.43 7.42,-11.43 7.435,-11.353 7.479,-11.289 7.543,-11.245 7.62,-11.23 7.62,-11.23 7.697,-11.245 7.761,-11.289 7.805,-11.353 7.82,-11.43
  Top Layer-L1 keep-out region: 6.55,-11.43 6.535,-11.507 6.491,-11.571 6.427,-11.615 6.35,-11.63 6.35,-11.63 6.273,-11.615 6.209,-11.571 6.165,-11.507 6.15,-11.43 6.15,-11.43 6.165,-11.353 6.209,-11.289 6.273,-11.245 6.35,-11.23 6.35,-11.23 6.427,-11.245 6.491,-11.289 6.535,-11.353 6.55,-11.43
  Top Layer-L1 keep-out region: 5.28,-11.43 5.265,-11.507 5.221,-11.571 5.157,-11.615 5.08,-11.63 5.08,-11.63 5.003,-11.615 4.939,-11.571 4.895,-11.507 4.88,-11.43 4.88,-11.43 4.895,-11.353 4.939,-11.289 5.003,-11.245 5.08,-11.23 5.08,-11.23 5.157,-11.245 5.221,-11.289 5.265,-11.353 5.28,-11.43
  Top Layer-L1 keep-out region: 4.01,-11.43 3.995,-11.507 3.951,-11.571 3.887,-11.615 3.81,-11.63 3.81,-11.63 3.733,-11.615 3.669,-11.571 3.625,-11.507 3.61,-11.43 3.61,-11.43 3.625,-11.353 3.669,-11.289 3.733,-11.245 3.81,-11.23 3.81,-11.23 3.887,-11.245 3.951,-11.289 3.995,-11.353 4.01,-11.43
  Top Layer-L1 keep-out region: 2.74,-11.43 2.725,-11.507 2.681,-11.571 2.617,-11.615 2.54,-11.63 2.54,-11.63 2.463,-11.615 2.399,-11.571 2.355,-11.507 2.34,-11.43 2.34,-11.43 2.355,-11.353 2.399,-11.289 2.463,-11.245 2.54,-11.23 2.54,-11.23 2.617,-11.245 2.681,-11.289 2.725,-11.353 2.74,-11.43
  Top Layer-L1 keep-out region: 1.47,-11.43 1.455,-11.507 1.411,-11.571 1.347,-11.615 1.27,-11.63 1.27,-11.63 1.193,-11.615 1.129,-11.571 1.085,-11.507 1.07,-11.43 1.07,-11.43 1.085,-11.353 1.129,-11.289 1.193,-11.245 1.27,-11.23 1.27,-11.23 1.347,-11.245 1.411,-11.289 1.455,-11.353 1.47,-11.43
  Top Layer-L1 keep-out region: 0.2,-11.43 0.185,-11.507 0.141,-11.571 0.077,-11.615 0,-11.63 0,-11.63 -0.077,-11.615 -0.141,-11.571 -0.185,-11.507 -0.2,-11.43 -0.2,-11.43 -0.185,-11.353 -0.141,-11.289 -0.077,-11.245 0,-11.23 0,-11.23 0.077,-11.245 0.141,-11.289 0.185,-11.353 0.2,-11.43
  Top Layer-L1 keep-out region: -1.07,-11.43 -1.085,-11.507 -1.129,-11.571 -1.193,-11.615 -1.27,-11.63 -1.27,-11.63 -1.347,-11.615 -1.411,-11.571 -1.455,-11.507 -1.47,-11.43 -1.47,-11.43 -1.455,-11.353 -1.411,-11.289 -1.347,-11.245 -1.27,-11.23 -1.27,-11.23 -1.193,-11.245 -1.129,-11.289 -1.085,-11.353 -1.07,-11.43
  Top Layer-L1 keep-out region: -2.34,-11.43 -2.355,-11.507 -2.399,-11.571 -2.463,-11.615 -2.54,-11.63 -2.54,-11.63 -2.617,-11.615 -2.681,-11.571 -2.725,-11.507 -2.74,-11.43 -2.74,-11.43 -2.725,-11.353 -2.681,-11.289 -2.617,-11.245 -2.54,-11.23 -2.54,-11.23 -2.463,-11.245 -2.399,-11.289 -2.355,-11.353 -2.34,-11.43
  Top Layer-L1 keep-out region: -3.61,-11.43 -3.625,-11.507 -3.669,-11.571 -3.733,-11.615 -3.81,-11.63 -3.81,-11.63 -3.887,-11.615 -3.951,-11.571 -3.995,-11.507 -4.01,-11.43 -4.01,-11.43 -3.995,-11.353 -3.951,-11.289 -3.887,-11.245 -3.81,-11.23 -3.81,-11.23 -3.733,-11.245 -3.669,-11.289 -3.625,-11.353 -3.61,-11.43
  Top Layer-L1 keep-out region: -4.88,-11.43 -4.895,-11.507 -4.939,-11.571 -5.003,-11.615 -5.08,-11.63 -5.08,-11.63 -5.157,-11.615 -5.221,-11.571 -5.265,-11.507 -5.28,-11.43 -5.28,-11.43 -5.265,-11.353 -5.221,-11.289 -5.157,-11.245 -5.08,-11.23 -5.08,-11.23 -5.003,-11.245 -4.939,-11.289 -4.895,-11.353 -4.88,-11.43
  Top Layer-L1 keep-out region: -6.15,-11.43 -6.165,-11.507 -6.209,-11.571 -6.273,-11.615 -6.35,-11.63 -6.35,-11.63 -6.427,-11.615 -6.491,-11.571 -6.535,-11.507 -6.55,-11.43 -6.55,-11.43 -6.535,-11.353 -6.491,-11.289 -6.427,-11.245 -6.35,-11.23 -6.35,-11.23 -6.273,-11.245 -6.209,-11.289 -6.165,-11.353 -6.15,-11.43
  Top Layer-L1 keep-out region: -7.42,-11.43 -7.435,-11.507 -7.479,-11.571 -7.543,-11.615 -7.62,-11.63 -7.62,-11.63 -7.697,-11.615 -7.761,-11.571 -7.805,-11.507 -7.82,-11.43 -7.82,-11.43 -7.805,-11.353 -7.761,-11.289 -7.697,-11.245 -7.62,-11.23 -7.62,-11.23 -7.543,-11.245 -7.479,-11.289 -7.435,-11.353 -7.42,-11.43
  Top Layer-L1 keep-out region: -8.69,-11.43 -8.705,-11.507 -8.749,-11.571 -8.813,-11.615 -8.89,-11.63 -8.89,-11.63 -8.967,-11.615 -9.031,-11.571 -9.075,-11.507 -9.09,-11.43 -9.09,-11.43 -9.075,-11.353 -9.031,-11.289 -8.967,-11.245 -8.89,-11.23 -8.89,-11.23 -8.813,-11.245 -8.749,-11.289 -8.705,-11.353 -8.69,-11.43
  Top Layer-L1 keep-out region: -9.96,-11.43 -9.975,-11.507 -10.019,-11.571 -10.083,-11.615 -10.16,-11.63 -10.16,-11.63 -10.237,-11.615 -10.301,-11.571 -10.345,-11.507 -10.36,-11.43 -10.36,-11.43 -10.345,-11.353 -10.301,-11.289 -10.237,-11.245 -10.16,-11.23 -10.16,-11.23 -10.083,-11.245 -10.019,-11.289 -9.975,-11.353 -9.96,-11.43
  Top Layer-L1 keep-out region: -11.23,-11.43 -11.245,-11.507 -11.289,-11.571 -11.353,-11.615 -11.43,-11.63 -11.43,-11.63 -11.507,-11.615 -11.571,-11.571 -11.615,-11.507 -11.63,-11.43 -11.63,-11.43 -11.615,-11.353 -11.571,-11.289 -11.507,-11.245 -11.43,-11.23 -11.43,-11.23 -11.353,-11.245 -11.289,-11.289 -11.245,-11.353 -11.23,-11.43
  Top Layer-L1 keep-out region: -12.5,-11.43 -12.515,-11.507 -12.559,-11.571 -12.623,-11.615 -12.7,-11.63 -12.7,-11.63 -12.777,-11.615 -12.841,-11.571 -12.885,-11.507 -12.9,-11.43 -12.9,-11.43 -12.885,-11.353 -12.841,-11.289 -12.777,-11.245 -12.7,-11.23 -12.7,-11.23 -12.623,-11.245 -12.559,-11.289 -12.515,-11.353 -12.5,-11.43
  Top Layer-L1 keep-out region: -13.77,-11.43 -13.785,-11.507 -13.829,-11.571 -13.893,-11.615 -13.97,-11.63 -13.97,-11.63 -14.047,-11.615 -14.111,-11.571 -14.155,-11.507 -14.17,-11.43 -14.17,-11.43 -14.155,-11.353 -14.111,-11.289 -14.047,-11.245 -13.97,-11.23 -13.97,-11.23 -13.893,-11.245 -13.829,-11.289 -13.785,-11.353 -13.77,-11.43
  Top Layer-L1 keep-out region: -15.04,-11.43 -15.055,-11.507 -15.099,-11.571 -15.163,-11.615 -15.24,-11.63 -15.24,-11.63 -15.317,-11.615 -15.381,-11.571 -15.425,-11.507 -15.44,-11.43 -15.44,-11.43 -15.425,-11.353 -15.381,-11.289 -15.317,-11.245 -15.24,-11.23 -15.24,-11.23 -15.163,-11.245 -15.099,-11.289 -15.055,-11.353 -15.04,-11.43
  Top Layer-L1 keep-out region: -16.31,-11.43 -16.325,-11.507 -16.369,-11.571 -16.433,-11.615 -16.51,-11.63 -16.51,-11.63 -16.587,-11.615 -16.651,-11.571 -16.695,-11.507 -16.71,-11.43 -16.71,-11.43 -16.695,-11.353 -16.651,-11.289 -16.587,-11.245 -16.51,-11.23 -16.51,-11.23 -16.433,-11.245 -16.369,-11.289 -16.325,-11.353 -16.31,-11.43
  Top Layer-L1 keep-out region: -17.58,-11.43 -17.595,-11.507 -17.639,-11.571 -17.703,-11.615 -17.78,-11.63 -17.78,-11.63 -17.857,-11.615 -17.921,-11.571 -17.965,-11.507 -17.98,-11.43 -17.98,-11.43 -17.965,-11.353 -17.921,-11.289 -17.857,-11.245 -17.78,-11.23 -17.78,-11.23 -17.703,-11.245 -17.639,-11.289 -17.595,-11.353 -17.58,-11.43
  Top Layer-L1 keep-out region: -17.58,11.43 -17.595,11.507 -17.639,11.571 -17.703,11.615 -17.78,11.63 -17.78,11.63 -17.857,11.615 -17.921,11.571 -17.965,11.507 -17.98,11.43 -17.98,11.43 -17.965,11.353 -17.921,11.289 -17.857,11.245 -17.78,11.23 -17.78,11.23 -17.703,11.245 -17.639,11.289 -17.595,11.353 -17.58,11.43
  Top Layer-L1 keep-out region: -16.31,11.43 -16.325,11.507 -16.369,11.571 -16.433,11.615 -16.51,11.63 -16.51,11.63 -16.587,11.615 -16.651,11.571 -16.695,11.507 -16.71,11.43 -16.71,11.43 -16.695,11.353 -16.651,11.289 -16.587,11.245 -16.51,11.23 -16.51,11.23 -16.433,11.245 -16.369,11.289 -16.325,11.353 -16.31,11.43
  Top Layer-L1 keep-out region: -15.04,11.43 -15.055,11.507 -15.099,11.571 -15.163,11.615 -15.24,11.63 -15.24,11.63 -15.317,11.615 -15.381,11.571 -15.425,11.507 -15.44,11.43 -15.44,11.43 -15.425,11.353 -15.381,11.289 -15.317,11.245 -15.24,11.23 -15.24,11.23 -15.163,11.245 -15.099,11.289 -15.055,11.353 -15.04,11.43
  Top Layer-L1 keep-out region: -13.77,11.43 -13.785,11.507 -13.829,11.571 -13.893,11.615 -13.97,11.63 -13.97,11.63 -14.047,11.615 -14.111,11.571 -14.155,11.507 -14.17,11.43 -14.17,11.43 -14.155,11.353 -14.111,11.289 -14.047,11.245 -13.97,11.23 -13.97,11.23 -13.893,11.245 -13.829,11.289 -13.785,11.353 -13.77,11.43
  Top Layer-L1 keep-out region: -12.5,11.43 -12.515,11.507 -12.559,11.571 -12.623,11.615 -12.7,11.63 -12.7,11.63 -12.777,11.615 -12.841,11.571 -12.885,11.507 -12.9,11.43 -12.9,11.43 -12.885,11.353 -12.841,11.289 -12.777,11.245 -12.7,11.23 -12.7,11.23 -12.623,11.245 -12.559,11.289 -12.515,11.353 -12.5,11.43
  Top Layer-L1 keep-out region: -11.23,11.43 -11.245,11.507 -11.289,11.571 -11.353,11.615 -11.43,11.63 -11.43,11.63 -11.507,11.615 -11.571,11.571 -11.615,11.507 -11.63,11.43 -11.63,11.43 -11.615,11.353 -11.571,11.289 -11.507,11.245 -11.43,11.23 -11.43,11.23 -11.353,11.245 -11.289,11.289 -11.245,11.353 -11.23,11.43
  Top Layer-L1 keep-out region: -9.96,11.43 -9.975,11.507 -10.019,11.571 -10.083,11.615 -10.16,11.63 -10.16,11.63 -10.237,11.615 -10.301,11.571 -10.345,11.507 -10.36,11.43 -10.36,11.43 -10.345,11.353 -10.301,11.289 -10.237,11.245 -10.16,11.23 -10.16,11.23 -10.083,11.245 -10.019,11.289 -9.975,11.353 -9.96,11.43
  Top Layer-L1 keep-out region: -8.69,11.43 -8.705,11.507 -8.749,11.571 -8.813,11.615 -8.89,11.63 -8.89,11.63 -8.967,11.615 -9.031,11.571 -9.075,11.507 -9.09,11.43 -9.09,11.43 -9.075,11.353 -9.031,11.289 -8.967,11.245 -8.89,11.23 -8.89,11.23 -8.813,11.245 -8.749,11.289 -8.705,11.353 -8.69,11.43
  Top Layer-L1 keep-out region: -7.42,11.43 -7.435,11.507 -7.479,11.571 -7.543,11.615 -7.62,11.63 -7.62,11.63 -7.697,11.615 -7.761,11.571 -7.805,11.507 -7.82,11.43 -7.82,11.43 -7.805,11.353 -7.761,11.289 -7.697,11.245 -7.62,11.23 -7.62,11.23 -7.543,11.245 -7.479,11.289 -7.435,11.353 -7.42,11.43
  Top Layer-L1 keep-out region: -6.15,11.43 -6.165,11.507 -6.209,11.571 -6.273,11.615 -6.35,11.63 -6.35,11.63 -6.427,11.615 -6.491,11.571 -6.535,11.507 -6.55,11.43 -6.55,11.43 -6.535,11.353 -6.491,11.289 -6.427,11.245 -6.35,11.23 -6.35,11.23 -6.273,11.245 -6.209,11.289 -6.165,11.353 -6.15,11.43
  Top Layer-L1 keep-out region: -4.88,11.43 -4.895,11.507 -4.939,11.571 -5.003,11.615 -5.08,11.63 -5.08,11.63 -5.157,11.615 -5.221,11.571 -5.265,11.507 -5.28,11.43 -5.28,11.43 -5.265,11.353 -5.221,11.289 -5.157,11.245 -5.08,11.23 -5.08,11.23 -5.003,11.245 -4.939,11.289 -4.895,11.353 -4.88,11.43
  Top Layer-L1 keep-out region: -3.61,11.43 -3.625,11.507 -3.669,11.571 -3.733,11.615 -3.81,11.63 -3.81,11.63 -3.887,11.615 -3.951,11.571 -3.995,11.507 -4.01,11.43 -4.01,11.43 -3.995,11.353 -3.951,11.289 -3.887,11.245 -3.81,11.23 -3.81,11.23 -3.733,11.245 -3.669,11.289 -3.625,11.353 -3.61,11.43
  Top Layer-L1 keep-out region: -2.34,11.43 -2.355,11.507 -2.399,11.571 -2.463,11.615 -2.54,11.63 -2.54,11.63 -2.617,11.615 -2.681,11.571 -2.725,11.507 -2.74,11.43 -2.74,11.43 -2.725,11.353 -2.681,11.289 -2.617,11.245 -2.54,11.23 -2.54,11.23 -2.463,11.245 -2.399,11.289 -2.355,11.353 -2.34,11.43
  Top Layer-L1 keep-out region: -1.07,11.43 -1.085,11.507 -1.129,11.571 -1.193,11.615 -1.27,11.63 -1.27,11.63 -1.347,11.615 -1.411,11.571 -1.455,11.507 -1.47,11.43 -1.47,11.43 -1.455,11.353 -1.411,11.289 -1.347,11.245 -1.27,11.23 -1.27,11.23 -1.193,11.245 -1.129,11.289 -1.085,11.353 -1.07,11.43
  Top Layer-L1 keep-out region: 0.2,11.43 0.185,11.507 0.141,11.571 0.077,11.615 0,11.63 0,11.63 -0.077,11.615 -0.141,11.571 -0.185,11.507 -0.2,11.43 -0.2,11.43 -0.185,11.353 -0.141,11.289 -0.077,11.245 0,11.23 0,11.23 0.077,11.245 0.141,11.289 0.185,11.353 0.2,11.43
  Top Layer-L1 keep-out region: 1.47,11.43 1.455,11.507 1.411,11.571 1.347,11.615 1.27,11.63 1.27,11.63 1.193,11.615 1.129,11.571 1.085,11.507 1.07,11.43 1.07,11.43 1.085,11.353 1.129,11.289 1.193,11.245 1.27,11.23 1.27,11.23 1.347,11.245 1.411,11.289 1.455,11.353 1.47,11.43
  Top Layer-L1 keep-out region: 2.74,11.43 2.725,11.507 2.681,11.571 2.617,11.615 2.54,11.63 2.54,11.63 2.463,11.615 2.399,11.571 2.355,11.507 2.34,11.43 2.34,11.43 2.355,11.353 2.399,11.289 2.463,11.245 2.54,11.23 2.54,11.23 2.617,11.245 2.681,11.289 2.725,11.353 2.74,11.43
  Top Layer-L1 keep-out region: 4.01,11.43 3.995,11.507 3.951,11.571 3.887,11.615 3.81,11.63 3.81,11.63 3.733,11.615 3.669,11.571 3.625,11.507 3.61,11.43 3.61,11.43 3.625,11.353 3.669,11.289 3.733,11.245 3.81,11.23 3.81,11.23 3.887,11.245 3.951,11.289 3.995,11.353 4.01,11.43
  Top Layer-L1 keep-out region: 5.28,11.43 5.265,11.507 5.221,11.571 5.157,11.615 5.08,11.63 5.08,11.63 5.003,11.615 4.939,11.571 4.895,11.507 4.88,11.43 4.88,11.43 4.895,11.353 4.939,11.289 5.003,11.245 5.08,11.23 5.08,11.23 5.157,11.245 5.221,11.289 5.265,11.353 5.28,11.43
  Top Layer-L1 keep-out region: 6.55,11.43 6.535,11.507 6.491,11.571 6.427,11.615 6.35,11.63 6.35,11.63 6.273,11.615 6.209,11.571 6.165,11.507 6.15,11.43 6.15,11.43 6.165,11.353 6.209,11.289 6.273,11.245 6.35,11.23 6.35,11.23 6.427,11.245 6.491,11.289 6.535,11.353 6.55,11.43
  Top Layer-L1 keep-out region: 7.82,11.43 7.805,11.507 7.761,11.571 7.697,11.615 7.62,11.63 7.62,11.63 7.543,11.615 7.479,11.571 7.435,11.507 7.42,11.43 7.42,11.43 7.435,11.353 7.479,11.289 7.543,11.245 7.62,11.23 7.62,11.23 7.697,11.245 7.761,11.289 7.805,11.353 7.82,11.43
  Top Layer-L1 keep-out region: 9.09,11.43 9.075,11.507 9.031,11.571 8.967,11.615 8.89,11.63 8.89,11.63 8.813,11.615 8.749,11.571 8.705,11.507 8.69,11.43 8.69,11.43 8.705,11.353 8.749,11.289 8.813,11.245 8.89,11.23 8.89,11.23 8.967,11.245 9.031,11.289 9.075,11.353 9.09,11.43
  Top Layer-L1 keep-out region: 10.36,11.43 10.345,11.507 10.301,11.571 10.237,11.615 10.16,11.63 10.16,11.63 10.083,11.615 10.019,11.571 9.975,11.507 9.96,11.43 9.96,11.43 9.975,11.353 10.019,11.289 10.083,11.245 10.16,11.23 10.16,11.23 10.237,11.245 10.301,11.289 10.345,11.353 10.36,11.43
  Top Layer-L1 keep-out region: 11.63,11.43 11.615,11.507 11.571,11.571 11.507,11.615 11.43,11.63 11.43,11.63 11.353,11.615 11.289,11.571 11.245,11.507 11.23,11.43 11.23,11.43 11.245,11.353 11.289,11.289 11.353,11.245 11.43,11.23 11.43,11.23 11.507,11.245 11.571,11.289 11.615,11.353 11.63,11.43
  Top Layer-L1 keep-out region: 12.9,11.43 12.885,11.507 12.841,11.571 12.777,11.615 12.7,11.63 12.7,11.63 12.623,11.615 12.559,11.571 12.515,11.507 12.5,11.43 12.5,11.43 12.515,11.353 12.559,11.289 12.623,11.245 12.7,11.23 12.7,11.23 12.777,11.245 12.841,11.289 12.885,11.353 12.9,11.43
  Top Layer-L1 keep-out region: 14.17,11.43 14.155,11.507 14.111,11.571 14.047,11.615 13.97,11.63 13.97,11.63 13.893,11.615 13.829,11.571 13.785,11.507 13.77,11.43 13.77,11.43 13.785,11.353 13.829,11.289 13.893,11.245 13.97,11.23 13.97,11.23 14.047,11.245 14.111,11.289 14.155,11.353 14.17,11.43
  Top Layer-L1 keep-out region: 15.44,11.43 15.425,11.507 15.381,11.571 15.317,11.615 15.24,11.63 15.24,11.63 15.163,11.615 15.099,11.571 15.055,11.507 15.04,11.43 15.04,11.43 15.055,11.353 15.099,11.289 15.163,11.245 15.24,11.23 15.24,11.23 15.317,11.245 15.381,11.289 15.425,11.353 15.44,11.43
  Top Layer-L1 keep-out region: 16.71,11.43 16.695,11.507 16.651,11.571 16.587,11.615 16.51,11.63 16.51,11.63 16.433,11.615 16.369,11.571 16.325,11.507 16.31,11.43 16.31,11.43 16.325,11.353 16.369,11.289 16.433,11.245 16.51,11.23 16.51,11.23 16.587,11.245 16.651,11.289 16.695,11.353 16.71,11.43
  Top Layer-L1 keep-out region: 17.98,11.43 17.965,11.507 17.921,11.571 17.857,11.615 17.78,11.63 17.78,11.63 17.703,11.615 17.639,11.571 17.595,11.507 17.58,11.43 17.58,11.43 17.595,11.353 17.639,11.289 17.703,11.245 17.78,11.23 17.78,11.23 17.857,11.245 17.921,11.289 17.965,11.353 17.98,11.43
  Top Layer-L1 keep-out region: -17.58,12.7 -17.595,12.777 -17.639,12.841 -17.703,12.885 -17.78,12.9 -17.78,12.9 -17.857,12.885 -17.921,12.841 -17.965,12.777 -17.98,12.7 -17.98,12.7 -17.965,12.623 -17.921,12.559 -17.857,12.515 -17.78,12.5 -17.78,12.5 -17.703,12.515 -17.639,12.559 -17.595,12.623 -17.58,12.7
  Top Layer-L1 keep-out region: -16.31,12.7 -16.325,12.777 -16.369,12.841 -16.433,12.885 -16.51,12.9 -16.51,12.9 -16.587,12.885 -16.651,12.841 -16.695,12.777 -16.71,12.7 -16.71,12.7 -16.695,12.623 -16.651,12.559 -16.587,12.515 -16.51,12.5 -16.51,12.5 -16.433,12.515 -16.369,12.559 -16.325,12.623 -16.31,12.7
  Top Layer-L1 keep-out region: -15.04,12.7 -15.055,12.777 -15.099,12.841 -15.163,12.885 -15.24,12.9 -15.24,12.9 -15.317,12.885 -15.381,12.841 -15.425,12.777 -15.44,12.7 -15.44,12.7 -15.425,12.623 -15.381,12.559 -15.317,12.515 -15.24,12.5 -15.24,12.5 -15.163,12.515 -15.099,12.559 -15.055,12.623 -15.04,12.7
  Top Layer-L1 keep-out region: -13.77,12.7 -13.785,12.777 -13.829,12.841 -13.893,12.885 -13.97,12.9 -13.97,12.9 -14.047,12.885 -14.111,12.841 -14.155,12.777 -14.17,12.7 -14.17,12.7 -14.155,12.623 -14.111,12.559 -14.047,12.515 -13.97,12.5 -13.97,12.5 -13.893,12.515 -13.829,12.559 -13.785,12.623 -13.77,12.7
  Top Layer-L1 keep-out region: -12.5,12.7 -12.515,12.777 -12.559,12.841 -12.623,12.885 -12.7,12.9 -12.7,12.9 -12.777,12.885 -12.841,12.841 -12.885,12.777 -12.9,12.7 -12.9,12.7 -12.885,12.623 -12.841,12.559 -12.777,12.515 -12.7,12.5 -12.7,12.5 -12.623,12.515 -12.559,12.559 -12.515,12.623 -12.5,12.7
  Top Layer-L1 keep-out region: -11.23,12.7 -11.245,12.777 -11.289,12.841 -11.353,12.885 -11.43,12.9 -11.43,12.9 -11.507,12.885 -11.571,12.841 -11.615,12.777 -11.63,12.7 -11.63,12.7 -11.615,12.623 -11.571,12.559 -11.507,12.515 -11.43,12.5 -11.43,12.5 -11.353,12.515 -11.289,12.559 -11.245,12.623 -11.23,12.7
  Top Layer-L1 keep-out region: -9.96,12.7 -9.975,12.777 -10.019,12.841 -10.083,12.885 -10.16,12.9 -10.16,12.9 -10.237,12.885 -10.301,12.841 -10.345,12.777 -10.36,12.7 -10.36,12.7 -10.345,12.623 -10.301,12.559 -10.237,12.515 -10.16,12.5 -10.16,12.5 -10.083,12.515 -10.019,12.559 -9.975,12.623 -9.96,12.7
  Top Layer-L1 keep-out region: -8.69,12.7 -8.705,12.777 -8.749,12.841 -8.813,12.885 -8.89,12.9 -8.89,12.9 -8.967,12.885 -9.031,12.841 -9.075,12.777 -9.09,12.7 -9.09,12.7 -9.075,12.623 -9.031,12.559 -8.967,12.515 -8.89,12.5 -8.89,12.5 -8.813,12.515 -8.749,12.559 -8.705,12.623 -8.69,12.7
  Top Layer-L1 keep-out region: -7.42,12.7 -7.435,12.777 -7.479,12.841 -7.543,12.885 -7.62,12.9 -7.62,12.9 -7.697,12.885 -7.761,12.841 -7.805,12.777 -7.82,12.7 -7.82,12.7 -7.805,12.623 -7.761,12.559 -7.697,12.515 -7.62,12.5 -7.62,12.5 -7.543,12.515 -7.479,12.559 -7.435,12.623 -7.42,12.7
  Top Layer-L1 keep-out region: -6.15,12.7 -6.165,12.777 -6.209,12.841 -6.273,12.885 -6.35,12.9 -6.35,12.9 -6.427,12.885 -6.491,12.841 -6.535,12.777 -6.55,12.7 -6.55,12.7 -6.535,12.623 -6.491,12.559 -6.427,12.515 -6.35,12.5 -6.35,12.5 -6.273,12.515 -6.209,12.559 -6.165,12.623 -6.15,12.7
  Top Layer-L1 keep-out region: -4.88,12.7 -4.895,12.777 -4.939,12.841 -5.003,12.885 -5.08,12.9 -5.08,12.9 -5.157,12.885 -5.221,12.841 -5.265,12.777 -5.28,12.7 -5.28,12.7 -5.265,12.623 -5.221,12.559 -5.157,12.515 -5.08,12.5 -5.08,12.5 -5.003,12.515 -4.939,12.559 -4.895,12.623 -4.88,12.7
  Top Layer-L1 keep-out region: -3.61,12.7 -3.625,12.777 -3.669,12.841 -3.733,12.885 -3.81,12.9 -3.81,12.9 -3.887,12.885 -3.951,12.841 -3.995,12.777 -4.01,12.7 -4.01,12.7 -3.995,12.623 -3.951,12.559 -3.887,12.515 -3.81,12.5 -3.81,12.5 -3.733,12.515 -3.669,12.559 -3.625,12.623 -3.61,12.7
  Top Layer-L1 keep-out region: -2.34,12.7 -2.355,12.777 -2.399,12.841 -2.463,12.885 -2.54,12.9 -2.54,12.9 -2.617,12.885 -2.681,12.841 -2.725,12.777 -2.74,12.7 -2.74,12.7 -2.725,12.623 -2.681,12.559 -2.617,12.515 -2.54,12.5 -2.54,12.5 -2.463,12.515 -2.399,12.559 -2.355,12.623 -2.34,12.7
  Top Layer-L1 keep-out region: -1.07,12.7 -1.085,12.777 -1.129,12.841 -1.193,12.885 -1.27,12.9 -1.27,12.9 -1.347,12.885 -1.411,12.841 -1.455,12.777 -1.47,12.7 -1.47,12.7 -1.455,12.623 -1.411,12.559 -1.347,12.515 -1.27,12.5 -1.27,12.5 -1.193,12.515 -1.129,12.559 -1.085,12.623 -1.07,12.7
  Top Layer-L1 keep-out region: 0.2,12.7 0.185,12.777 0.141,12.841 0.077,12.885 0,12.9 0,12.9 -0.077,12.885 -0.141,12.841 -0.185,12.777 -0.2,12.7 -0.2,12.7 -0.185,12.623 -0.141,12.559 -0.077,12.515 0,12.5 0,12.5 0.077,12.515 0.141,12.559 0.185,12.623 0.2,12.7
  Top Layer-L1 keep-out region: 1.47,12.7 1.455,12.777 1.411,12.841 1.347,12.885 1.27,12.9 1.27,12.9 1.193,12.885 1.129,12.841 1.085,12.777 1.07,12.7 1.07,12.7 1.085,12.623 1.129,12.559 1.193,12.515 1.27,12.5 1.27,12.5 1.347,12.515 1.411,12.559 1.455,12.623 1.47,12.7
  Top Layer-L1 keep-out region: 2.74,12.7 2.725,12.777 2.681,12.841 2.617,12.885 2.54,12.9 2.54,12.9 2.463,12.885 2.399,12.841 2.355,12.777 2.34,12.7 2.34,12.7 2.355,12.623 2.399,12.559 2.463,12.515 2.54,12.5 2.54,12.5 2.617,12.515 2.681,12.559 2.725,12.623 2.74,12.7
  Top Layer-L1 keep-out region: 4.01,12.7 3.995,12.777 3.951,12.841 3.887,12.885 3.81,12.9 3.81,12.9 3.733,12.885 3.669,12.841 3.625,12.777 3.61,12.7 3.61,12.7 3.625,12.623 3.669,12.559 3.733,12.515 3.81,12.5 3.81,12.5 3.887,12.515 3.951,12.559 3.995,12.623 4.01,12.7
  Top Layer-L1 keep-out region: 5.28,12.7 5.265,12.777 5.221,12.841 5.157,12.885 5.08,12.9 5.08,12.9 5.003,12.885 4.939,12.841 4.895,12.777 4.88,12.7 4.88,12.7 4.895,12.623 4.939,12.559 5.003,12.515 5.08,12.5 5.08,12.5 5.157,12.515 5.221,12.559 5.265,12.623 5.28,12.7
  Top Layer-L1 keep-out region: 6.55,12.7 6.535,12.777 6.491,12.841 6.427,12.885 6.35,12.9 6.35,12.9 6.273,12.885 6.209,12.841 6.165,12.777 6.15,12.7 6.15,12.7 6.165,12.623 6.209,12.559 6.273,12.515 6.35,12.5 6.35,12.5 6.427,12.515 6.491,12.559 6.535,12.623 6.55,12.7
  Top Layer-L1 keep-out region: 7.82,12.7 7.805,12.777 7.761,12.841 7.697,12.885 7.62,12.9 7.62,12.9 7.543,12.885 7.479,12.841 7.435,12.777 7.42,12.7 7.42,12.7 7.435,12.623 7.479,12.559 7.543,12.515 7.62,12.5 7.62,12.5 7.697,12.515 7.761,12.559 7.805,12.623 7.82,12.7
  Top Layer-L1 keep-out region: 9.09,12.7 9.075,12.777 9.031,12.841 8.967,12.885 8.89,12.9 8.89,12.9 8.813,12.885 8.749,12.841 8.705,12.777 8.69,12.7 8.69,12.7 8.705,12.623 8.749,12.559 8.813,12.515 8.89,12.5 8.89,12.5 8.967,12.515 9.031,12.559 9.075,12.623 9.09,12.7
  Top Layer-L1 keep-out region: 10.36,12.7 10.345,12.777 10.301,12.841 10.237,12.885 10.16,12.9 10.16,12.9 10.083,12.885 10.019,12.841 9.975,12.777 9.96,12.7 9.96,12.7 9.975,12.623 10.019,12.559 10.083,12.515 10.16,12.5 10.16,12.5 10.237,12.515 10.301,12.559 10.345,12.623 10.36,12.7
